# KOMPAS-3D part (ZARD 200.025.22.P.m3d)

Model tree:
1. Поверхность без истории:1
2. Поверхность без истории:2
3. Поверхность без истории:3
4. Поверхность без истории:4
5. Поверхность без истории:5
6. Поверхность без истории:6
7. Поверхность без истории:7
8. Поверхность без истории:8
9. Поверхность без истории:9
10. Поверхность без истории:10
11. Поверхность без истории:11
12. Поверхность без истории:12
13. Поверхность без истории:13
14. Поверхность без истории:14
15. Поверхность без истории:15
16. Поверхность без истории:16
17. Поверхность без истории:17
18. Поверхность без истории:18
19. Поверхность без истории:19
20. Поверхность без истории:20
21. Поверхность без истории:21
22. Поверхность без истории:22
23. Поверхность без истории:23
24. Поверхность без истории:24
25. Поверхность без истории:25
26. Поверхность без истории:26
27. Поверхность без истории:27
28. Поверхность без истории:28
29. Поверхность без истории:29
30. Поверхность без истории:30
31. Поверхность без истории:31
32. Поверхность без истории:32
33. Поверхность без истории:33
34. Поверхность без истории:34
35. Поверхность без истории:35
36. Поверхность без истории:36
37. Поверхность без истории:37
38. Поверхность без истории:38
39. Поверхность без истории:39
40. Поверхность без истории:40
41. Поверхность без истории:41
42. Поверхность без истории:42
43. Поверхность без истории:43
44. Поверхность без истории:44
45. Поверхность без истории:45
46. Поверхность без истории:46
47. Поверхность без истории:47
48. Поверхность без истории:48
49. Поверхность без истории:49
50. Поверхность без истории:50
51. Поверхность без истории:51
52. Поверхность без истории:52
53. Поверхность без истории:53
54. Поверхность без истории:54
55. Поверхность без истории:55
56. Поверхность без истории:56
57. Поверхность без истории:57
58. Поверхность без истории:58
59. Поверхность без истории:59
60. Поверхность без истории:60
61. Поверхность без истории:61
62. Поверхность без истории:62
63. Поверхность без истории:63
64. Поверхность без истории:64
65. Поверхность без истории:65
66. Поверхность без истории:66
67. Поверхность без истории:67
68. Поверхность без истории:68
69. Поверхность без истории:69
70. Поверхность без истории:70
71. Поверхность без истории:71
72. Поверхность без истории:72
73. Поверхность без истории:73
74. Поверхность без истории:74
75. Поверхность без истории:75
76. Поверхность без истории:76
77. Поверхность без истории:77
78. Поверхность без истории:78
79. Поверхность без истории:79
80. Поверхность без истории:80
81. Поверхность без истории:81
82. Поверхность без истории:82
83. Поверхность без истории:83
84. Поверхность без истории:84
85. Поверхность без истории:85
86. Поверхность без истории:86
87. Поверхность без истории:87
88. Поверхность без истории:88
89. Поверхность без истории:89
90. Поверхность без истории:90
91. Поверхность без истории:91
92. Поверхность без истории:92
93. Поверхность без истории:93
94. Поверхность без истории:94
95. Поверхность без истории:95
96. Поверхность без истории:96
97. Поверхность без истории:97
98. Поверхность без истории:98
99. Поверхность без истории:99
100. Поверхность без истории:100
101. Поверхность без истории:101

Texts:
  ЗАРД 200.025.22-ХХ.Р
